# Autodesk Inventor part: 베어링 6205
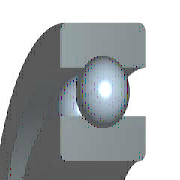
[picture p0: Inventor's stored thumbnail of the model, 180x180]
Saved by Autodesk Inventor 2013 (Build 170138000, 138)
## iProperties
Company: 한국ATC센터
IsCustomPart: 1
Created: 2009-02
Part Number: 베어링 6205
Material: 강, 연강
Description: 깊은 그루브 볼 베어링
Document SubType Name: Modeling
Standard: KS B 2023
Designer: KYOUNG IL JANG
Standards Organization: KS
Language: ko-KR
Size Designation: 6205 - 25 x 52 x 15
Categories: <MemberInstance><Categories><Category DisplayName="샤프트 부품" InternalName="7f7aeb1f-a693-4053-b835-cee3144e0d98" Mnemonic="SHFT"><Category DisplayName="베어링" Inter
Density: 1 g/cm^3
Author: KYOUNG IL JANG
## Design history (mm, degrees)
sketch "스케치" dims "d0" = 7.02 (= -0.26 x WD + 0.26 x BD)
  geometry: L1 (3.99, 19.25)-(11.01, 19.25); L2 (7.5, 19.25)-(7.5, 15.74); L3 (7.5, 19.25)-(7.5, 22.76); L4 (4.892, 16.901)-(0, 16.901); L5 (0, 12.5)-(15, 12.5); L6 (4.892, 21.599)-(0, 21.599); L7 (0, 26)-(15, 26); L8 (15, 12.5)-(15, 16.901); L9 (10.108, 16.901)-(15, 16.901); L10 (10.108, 21.599)-(15, 21.599); L11 (15, 26)-(15, 21.599); L12 (-1.4, 0)-(8.4, 0) reference; L13 (0, -0.3)-(0, 5.3) reference
  constraints: 22 end point, 4 point on line, 2 collinear, 2 perpendicular, 2 symmetric about line, 1 midpoint, 1 parallel, 14 other
  dimensions: "d9" = 25 diameter of L5 L12 (= WD); "d11" = 52 diameter of L7 L12 (= BD); "d12" = 15 distance between parallel lines of L8 L13 (= KB); "d13" = 33.802 diameter of L9 L12 (= 0.326 x BD + 0.674 x WD)
revolve "본체" stored, may be unused: angle "d6" = 90 deg
revolve "볼" stored, may be unused: angle "d7" = 90 deg
pattern_circular "IDS_ARRAYBALL[SIMPL:T]" dims angle "d3" = 360 deg
body "Solid1"
fillet "모깎기1" dims "d1" = 1 (= KRS)
other parameters: "WD" = 25 [user parameter; used in 5 equation terms], "BD" = 52 [user parameter; used in 5 equation terms], "KB" = 15 [user parameter; used in 1 equation term], "KRS" = 1 [user parameter; used in 1 equation term], "d4" = 0, "d5" = 0, "d8" = 0, "d14" = 0, "d15" = 0, "BBA" = 0 [user parameter], "BC0" = 7800000 [user parameter], "BC" = 1.4e+07 [user parameter], "BR" = 26 (= 0.5 x BD) [user parameter], "WR" = 12.5 (= 0.5 x WD) [user parameter]
